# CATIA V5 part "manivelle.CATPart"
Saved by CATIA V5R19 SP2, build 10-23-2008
Part number: manivelle
Publications: "epaisseur", "diamètre manivelle", "longueur manivelle", "petit entraxe", "diamètre pivot"
Bounding box of the stored display mesh (mm): x -5 to 25, y -10 to 110, z -10 to 10
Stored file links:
  C:\Users\pierre\Documents\IFMA\IAO\manivelle.CATPart
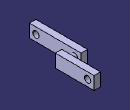
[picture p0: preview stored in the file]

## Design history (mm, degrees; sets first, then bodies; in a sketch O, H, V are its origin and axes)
Parameters
  epaisseur = 5 mm
  `diamètre manivelle` = 20 mm
  `longueur manivelle` = 100 mm
  `petit entraxe` = 40 mm
  `diamètre pivot` = 10 mm
Body1 (main body)
  Point1: (0, 0, 0)
  Point2: (0, 60 {= `longueur manivelle` -`petit entraxe`}, 0)
  Point3: (20 {= epaisseur *4}, 100 {= `longueur manivelle`}, 0)
  Plane1: type OffsetPt, RefPlane yz-plane, RefPoint Point3
  Point4: (20 {= epaisseur *4}, 60 {= `longueur manivelle` -`petit entraxe`}, 0)
  Line1: type PtPt, FirstPoint Point2, SecondPoint Point4
  Line2: type PtPt, FirstPoint Point1, SecondPoint Point2
  Line3: type PtPt, FirstPoint Point4, SecondPoint Point3
  Sketch1 on xy-plane, origin (0, 0, 0), H (1, 0, 0), V (0, 1, 0)
    line L1 (-5, -10) -> (-5, 70)
    line L2 (-5, 70) -> (15, 70)
    line L3 (15, 70) -> (15, 110)
    line L4 (15, 110) -> (25, 110)
    line L5 (25, 110) -> (25, 50)
    line L6 (25, 50) -> (5, 50)
    line L7 (5, 50) -> (5, -10)
    line L8 (5, -10) -> (-5, -10)
    reference projected line E1 (0, 0) -> (0, 60) from Line2
    reference projected line E2 (0, 60) -> (10, 60) from Line1
    reference projected line E3 (20, 60.6226) -> (20, 100.6226) from Line3
    reference projected point E4 (0, 0) from Point1
    reference projected point E5 (20, 100) from Point3
    distance L7 L1 = 10 {= epaisseur *2}
    distance L3 L5 = 10 {= epaisseur *2}
    distance L2 L6 = 20
    distance E4 L8 = 10 {= `diamètre manivelle` /2}
    distance L4 E5 = 10 {= `diamètre manivelle` /2}
    vertical: L1 V, L3 V, L5 V
    horizontal: L2 H, L4 H, L6 H, L8 H
    parallelism: L7 L5
    symmetry: L1 L7 E1, L6 L2 E2, L3 L5 E3
  Pad1: profile Sketch1, direction (0, 0, 1), length 10 {= `diamètre manivelle` /2}, mirrored extent
  Sketch2 on face of Pad1 from Sketch1.L5, origin (25, 0, 0), H (0, 1, 0), V (0, 0, 1)
    circle A1 centre (100, 0) radius 5
    point P1 (100, 0)
    circle A2 centre (0, 0) radius 5
    point P2 (0, 0)
    reference projected point E1 (100, 0) from Point3
    reference projected point E2 (0, 0) from Point1
    radius A2 = 5 {= `diamètre pivot` /2}
    radius A1 = 5 {= `diamètre pivot` /2}
    coincidence: P1 E1, P2 E2
  Pocket1: profile Sketch2, direction (-1, 0, 0), through (limit type 3)
  Point5: type Between, FirstPoint Point2, SecondPoint Point4, Ratio 0.5
  Plane2: type OffsetPt, RefPlane yz-plane, RefPoint Point5
  Sketch3 on Plane2, origin (10, 0, 0), H (0, 1, 0), V (0, 0, 1)
    circle A1 centre (60, 0) radius 5
    point P1 (60, 0)
    reference projected point E1 (60, 0) from Point5
    line L1 (50, 10) -> (70, 10)
    line L2 (70, 10) -> (70, -10)
    line L3 (70, -10) -> (50, -10)
    line L4 (50, -10) -> (50, 10)
    reference projected line E2 (50, 10) -> (110, 10) from edge [face of Pad1 from Sketch1.L5 | end face of Pad1]
    reference projected line E3 (50, -10) -> (50, 10) from edge [face of Pad1 from Sketch1.L5 | face of Pad1 from Sketch1.L6]
    distance L1 L3 = 20 {= `diamètre manivelle`}
    distance L2 L4 = 20 {= `diamètre manivelle`}
    radius A1 = 5 {= `diamètre pivot` /2}
    coincidence: P1 H, P1 E1, L1 E2, L4 E3
    horizontal: L1 H, L3 H
    vertical: L2 V, L4 V
  Pocket2: profile Sketch3, direction (-1, 0, 0), length 5 {= epaisseur}, mirrored extent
